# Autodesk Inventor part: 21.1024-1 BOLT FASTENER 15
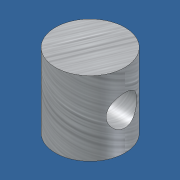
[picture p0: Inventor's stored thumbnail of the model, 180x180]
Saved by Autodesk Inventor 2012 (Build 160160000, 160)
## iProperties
Created: 2006-12
Part Number: 21.1024-1 BOLT FASTENER 15
Document SubType Name: Modeling
Designer: Andy Moles
Material: Aluminum-6061
Mass: 5.32319 g
Surface Area: 13.8617 cm^2
Volume: 1.96428 cm^3
Density: 2.71 g/cm^3
Author: Andy Moles
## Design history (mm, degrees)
sketch "Sketch1"
  geometry: C1 r 7.5 at (0, 0); 1 further point
  constraints: 1 centre point, 1 coincident
  dimensions: "d0" = 15 diameter of C1
extrude "Extrusion1" new body sketch "Sketch1" distance "d1" = 16; taper "d2" = 0 deg
workplane "Work Plane1"
sketch "Sketch2"
  geometry: L1 (7.5, 0)-(7.5, 16) reference; L2 (-7.5, 16)-(7.5, 16) reference; L3 (-7.5, 0)-(7.5, 0) reference; L4 (7.5, 16)-(-7.5, 0); C1 r 5.5 at (0, 8); 1 further point
  constraints: 2 end point, 1 centre point, 1 midpoint
  dimensions: "d3" = 11 diameter of C1
extrude "Extrusion2" cut sketch "Sketch2" distance "d4" = 6.7; taper "d5" = 0 deg
sketch "Sketch3"
  geometry: C1 r 5.5 at (0, 0) reference; C2 r 3.3 at (0, 0); 1 further point
  constraints: 1 centre point, 1 coincident
  dimensions: "d6" = 6.6 diameter of C2
extrude "Extrusion3" cut sketch "Sketch3" stored distance "d7" = 6.7; taper "d8" = 0 deg
body "Solid1"
node "Projected Loop1"
